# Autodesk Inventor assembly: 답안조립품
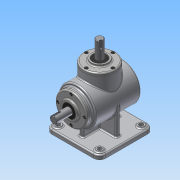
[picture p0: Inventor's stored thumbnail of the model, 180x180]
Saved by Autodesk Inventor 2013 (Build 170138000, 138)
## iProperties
Created: 2015-07
Part Number: 답안조립품
Document SubType Name: Assembly
Designer: Administrator
Author: Administrator
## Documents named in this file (14)
- C:\Users\Administrator\Desktop\450706V1021\답안조립품.iam
- C:\Users\Administrator\Desktop\450706V1021\M4.ipt
- C:\Users\Administrator\Desktop\450706V1021\메인 베벨기어.ipt
- C:\Users\Administrator\Desktop\450706V1021\메인 축.ipt
- 메인 축.ipt
- C:\Users\Administrator\Desktop\450706V1021\베어링 6203.ipt
- C:\Users\Administrator\Desktop\450706V1021\본체.ipt
- C:\Users\Administrator\Desktop\450706V1021\서브 베벨기어.ipt
- C:\Users\Administrator\Desktop\450706V1021\서브 축.ipt
- 서브 축.ipt
- C:\Users\Administrator\Desktop\450706V1021\오일실.ipt
- C:\Users\Administrator\Desktop\450706V1021\커버.ipt
- C:\Users\Administrator\Desktop\450706V1021\키 4x4.ipt
- C:\Users\Administrator\Desktop\450706V1021\키 5x5.ipt
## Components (8 placed, 1 different names)
1. M4:1
2. M4:3
3. M4:4
4. M4:5
5. M4:2
6. M4:6
7. M4:7
8. M4:8
